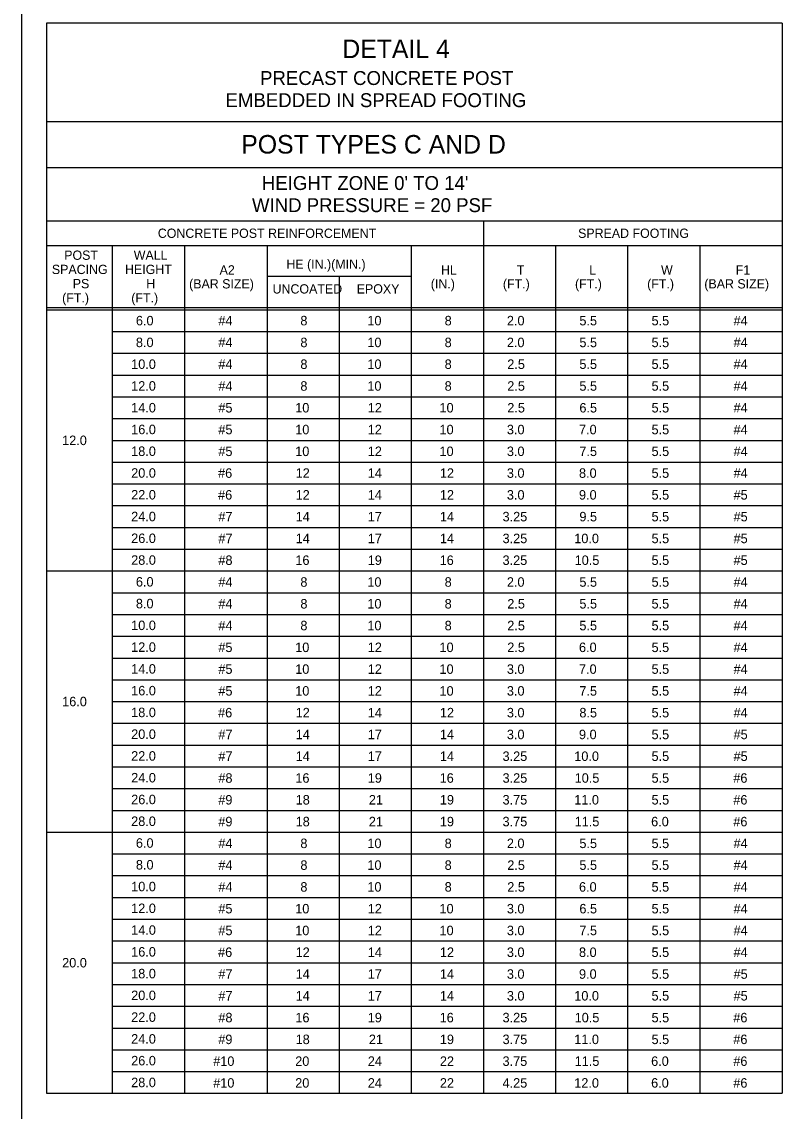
# Model space of a CAD drawing. Extents: x 3351 to 8430, y -3586 to 1457.
# Drawn here: x 6324.3 to 6570.3, y -2179.3 to -1826.9 of the extents above; entities that cross this region are included whole.
import ezdxf

# ---------------------------------------------------------------- set-up
doc = ezdxf.new("R2010")
doc.units = 0
doc.layers.add('1', color=7, linetype='Continuous')
doc.layers.add('2', color=7, linetype='Continuous')

msp = doc.modelspace()

# ---------------------------------------------------------------- linework, layer by layer
at = {"layer": '1'}
for p, q in [((6332.34, -1827.31), (6332.34, -2173.5)), ((6570.34, -1827.31), (6332.34, -1827.31)), ((6570.34, -1827.31), (6570.34, -2173.5)), ((6570.34, -1859.31), (6332.34, -1859.31)), ((6332.34, -1874.01), (6570.34, -1874.01)), ((6332.34, -1891.31), (6570.34, -1891.31)), ((6473.68, -1891.31), (6473.68, -2173.5)), ((6332.34, -1899.31), (6400.34, -1899.31)), ((6332.34, -1899.31), (6570.34, -1899.31)), ((6353.68, -2173.5), (6353.68, -1899.31)), ((6377.01, -1899.31), (6377.01, -2173.5)), ((6403.68, -1899.31), (6403.68, -2173.5)), ((6450.34, -1899.31), (6450.34, -2173.5)), ((6497.01, -1899.31), (6497.01, -2173.5)), ((6520.34, -1899.31), (6520.34, -2173.5)), ((6543.68, -1899.31), (6543.68, -2173.5)), ((6450.38, -1909.31), (6403.71, -1909.31)), ((6427.01, -1909.31), (6427.01, -2173.5)), ((6332.34, -1919.31), (6570.34, -1919.31)), ((6332.34, -1920.06), (6570.34, -1920.06)), ((6390.34, -1923.58), (6390.34, -1923.58)), ((6415.34, -1923.58), (6415.34, -1923.58)), ((6438.68, -1923.58), (6438.68, -1923.58)), ((6462.01, -1923.58), (6462.01, -1923.58)), ((6485.34, -1923.58), (6485.34, -1923.58)), ((6508.68, -1923.58), (6508.68, -1923.58)), ((6532.01, -1923.58), (6532.01, -1923.58)), ((6557.01, -1923.58), (6557.01, -1923.58)), ((6353.68, -1927.1), (6570.34, -1927.1)), ((6353.68, -1934.14), (6570.34, -1934.14)), ((6353.68, -1941.18), (6570.34, -1941.18)), ((6353.68, -1948.22), (6570.34, -1948.22)), ((6353.68, -1955.26), (6570.34, -1955.26)), ((6353.68, -1962.3), (6570.34, -1962.3)), ((6353.68, -1969.34), (6570.34, -1969.34)), ((6353.68, -1976.38), (6570.34, -1976.38)), ((6353.68, -1983.42), (6570.34, -1983.42)), ((6353.68, -1990.46), (6570.34, -1990.46)), ((6353.68, -1997.5), (6570.34, -1997.5)), ((6332.34, -2004.54), (6570.34, -2004.54)), ((6390.34, -2008.06), (6390.34, -2008.06)), ((6415.34, -2008.06), (6415.34, -2008.06)), ((6438.68, -2008.06), (6438.68, -2008.06)), ((6462.01, -2008.06), (6462.01, -2008.06)), ((6485.34, -2008.06), (6485.34, -2008.06)), ((6508.68, -2008.06), (6508.68, -2008.06)), ((6532.01, -2008.06), (6532.01, -2008.06)), ((6557.01, -2008.06), (6557.01, -2008.06)), ((6353.68, -2011.58), (6570.34, -2011.58)), ((6353.68, -2018.62), (6570.34, -2018.62)), ((6353.68, -2025.66), (6570.34, -2025.66)), ((6353.68, -2032.7), (6570.34, -2032.7)), ((6353.68, -2039.74), (6570.34, -2039.74)), ((6353.68, -2046.78), (6570.34, -2046.78)), ((6353.68, -2053.82), (6570.34, -2053.82)), ((6353.68, -2060.86), (6570.34, -2060.86)), ((6353.68, -2067.9), (6570.34, -2067.9)), ((6353.68, -2074.94), (6570.34, -2074.94)), ((6353.68, -2081.98), (6570.34, -2081.98)), ((6332.34, -2089.02), (6570.34, -2089.02)), ((6390.34, -2092.54), (6390.34, -2092.54)), ((6415.34, -2092.54), (6415.34, -2092.54)), ((6438.68, -2092.54), (6438.68, -2092.54)), ((6462.01, -2092.54), (6462.01, -2092.54)), ((6485.34, -2092.54), (6485.34, -2092.54)), ((6508.68, -2092.54), (6508.68, -2092.54)), ((6532.01, -2092.54), (6532.01, -2092.54)), ((6557.01, -2092.54), (6557.01, -2092.54)), ((6353.68, -2096.06), (6570.34, -2096.06)), ((6353.68, -2103.1), (6570.34, -2103.1)), ((6353.68, -2110.14), (6570.34, -2110.14)), ((6353.68, -2117.18), (6570.34, -2117.18)), ((6353.68, -2124.22), (6570.34, -2124.22)), ((6353.68, -2131.26), (6570.34, -2131.26)), ((6353.68, -2138.3), (6570.34, -2138.3)), ((6353.68, -2145.34), (6570.34, -2145.34)), ((6353.68, -2152.38), (6570.34, -2152.38)), ((6353.68, -2159.42), (6570.34, -2159.42)), ((6353.68, -2166.46), (6570.34, -2166.46)), ((6332.34, -2173.5), (6570.34, -2173.5))]:
    msp.add_line(p, q, dxfattribs=at)
at = {"layer": '2'}
msp.add_line((6324.34, -2383.31), (6324.34, -1819.31), dxfattribs=at)

# ---------------------------------------------------------------- texts
at = {"layer": '1'}
for s, height, p in [('DETAIL 4', 6, (6428.03, -1838.66)), ('PRECAST CONCRETE POST', 4.5, (6401.42, -1847.36)), ('EMBEDDED IN SPREAD FOOTING', 4.5, (6390.26, -1854.52)), ('POST TYPES C AND D', 6, (6395.34, -1869.54)), ("HEIGHT ZONE 0' TO 14'", 4.5, (6402, -1881.32)), ('WIND PRESSURE = 20 PSF', 4.5, (6398.81, -1888.48)), ('CONCRETE POST REINFORCEMENT', 3, (6368.35, -1896.81)), ('SPREAD FOOTING', 3, (6504.3, -1896.81)), ('POST', 3, (6338.07, -1903.91)), ('WALL', 3, (6360.56, -1903.91)), ('SPACING', 3, (6334.07, -1908.51)), ('HEIGHT', 3, (6357.73, -1908.51)), ('A2', 3, (6388.34, -1908.67)), ('HE (IN.)(MIN.)', 3, (6409.94, -1906.81)), ('HL', 3, (6459.97, -1908.67)), ('T', 3, (6484.49, -1908.67)), ('L', 3, (6507.94, -1908.67)), ('W', 3, (6531.14, -1908.67)), ('F1', 3, (6555.3, -1908.67)), ('PS', 3, (6340.83, -1913.11)), ('H', 3, (6364.61, -1913.11)), ('(BAR SIZE)', 3, (6378.47, -1913.17)), ('UNCOATED', 3, (6405.47, -1914.81)), ('EPOXY', 3, (6432.69, -1914.81)), ('(IN.)', 3, (6456.65, -1913.17)), ('(FT.)', 3, (6479.98, -1913.17)), ('(FT.)', 3, (6503.31, -1913.17)), ('(FT.)', 3, (6526.65, -1913.17)), ('(BAR SIZE)', 3, (6545.14, -1913.17)), ('(FT.)', 3, (6337.4, -1917.71)), ('(FT.)', 3, (6359.76, -1917.71)), ('6.0', 3.07, (6361.26, -1925.11)), ('#4', 3.07, (6387.94, -1925.11)), ('8', 3.07, (6414.47, -1925.11)), ('10', 3.07, (6436.14, -1925.11)), ('8', 3.07, (6461.14, -1925.11)), ('2.0', 3.07, (6481.27, -1925.11)), ('5.5', 3.07, (6504.73, -1925.11)), ('5.5', 3.07, (6528.07, -1925.11)), ('#4', 3.07, (6554.6, -1925.11)), ('8.0', 3.07, (6361.26, -1932.15)), ('#4', 3.07, (6387.94, -1932.16)), ('8', 3.07, (6414.47, -1932.16)), ('10', 3.07, (6436.14, -1932.16)), ('8', 3.07, (6461.14, -1932.16)), ('2.0', 3.07, (6481.27, -1932.16)), ('5.5', 3.07, (6504.73, -1932.16)), ('5.5', 3.07, (6528.07, -1932.16)), ('#4', 3.07, (6554.6, -1932.16)), ('10.0', 3.07, (6359.73, -1939.19)), ('#4', 3.07, (6387.94, -1939.2)), ('8', 3.07, (6414.47, -1939.2)), ('10', 3.07, (6436.14, -1939.2)), ('8', 3.07, (6461.14, -1939.2)), ('2.5', 3.07, (6481.4, -1939.2)), ('5.5', 3.07, (6504.73, -1939.2)), ('5.5', 3.07, (6528.07, -1939.2)), ('#4', 3.07, (6554.6, -1939.2)), ('12.0', 3.07, (6359.73, -1946.23)), ('#4', 3.07, (6387.94, -1946.25)), ('8', 3.07, (6414.47, -1946.25)), ('10', 3.07, (6436.14, -1946.25)), ('8', 3.07, (6461.14, -1946.25)), ('2.5', 3.07, (6481.4, -1946.25)), ('5.5', 3.07, (6504.73, -1946.25)), ('5.5', 3.07, (6528.07, -1946.25)), ('#4', 3.07, (6554.6, -1946.25)), ('14.0', 3.07, (6359.73, -1953.27)), ('#5', 3.07, (6387.94, -1953.29)), ('10', 3.07, (6412.8, -1953.29)), ('12', 3.07, (6436.27, -1953.29)), ('10', 3.07, (6459.47, -1953.29)), ('2.5', 3.07, (6481.4, -1953.29)), ('6.5', 3.07, (6504.73, -1953.29)), ('5.5', 3.07, (6528.07, -1953.29)), ('#4', 3.07, (6554.6, -1953.29)), ('16.0', 3.07, (6359.73, -1960.31)), ('#5', 3.07, (6387.94, -1960.34)), ('10', 3.07, (6412.8, -1960.34)), ('12', 3.07, (6436.27, -1960.34)), ('10', 3.07, (6459.47, -1960.34)), ('3.0', 3.07, (6481.27, -1960.34)), ('7.0', 3.07, (6504.6, -1960.34)), ('5.5', 3.07, (6528.07, -1960.34)), ('#4', 3.07, (6554.6, -1960.34)), ('12.0', 3.07, (6337.4, -1963.83)), ('18.0', 3.07, (6359.73, -1967.35)), ('#5', 3.07, (6387.94, -1967.38)), ('10', 3.07, (6412.8, -1967.38)), ('12', 3.07, (6436.27, -1967.38)), ('10', 3.07, (6459.47, -1967.38)), ('3.0', 3.07, (6481.27, -1967.38)), ('7.5', 3.07, (6504.73, -1967.38)), ('5.5', 3.07, (6528.07, -1967.38)), ('#4', 3.07, (6554.6, -1967.38)), ('20.0', 3.07, (6359.73, -1974.39)), ('#6', 3.07, (6387.85, -1974.42)), ('12', 3.07, (6412.94, -1974.42)), ('14', 3.07, (6436.27, -1974.42)), ('12', 3.07, (6459.6, -1974.42)), ('3.0', 3.07, (6481.27, -1974.42)), ('8.0', 3.07, (6504.6, -1974.42)), ('5.5', 3.07, (6528.07, -1974.42)), ('#4', 3.07, (6554.6, -1974.42)), ('22.0', 3.07, (6359.73, -1981.43)), ('#6', 3.07, (6387.85, -1981.47)), ('12', 3.07, (6412.94, -1981.47)), ('14', 3.07, (6436.27, -1981.47)), ('12', 3.07, (6459.6, -1981.47)), ('3.0', 3.07, (6481.27, -1981.47)), ('9.0', 3.07, (6504.6, -1981.47)), ('5.5', 3.07, (6528.07, -1981.47)), ('#5', 3.07, (6554.6, -1981.47)), ('24.0', 3.07, (6359.73, -1988.47)), ('#7', 3.07, (6387.94, -1988.51)), ('14', 3.07, (6412.94, -1988.51)), ('17', 3.07, (6436.27, -1988.51)), ('14', 3.07, (6459.6, -1988.51)), ('3.25', 3.07, (6479.87, -1988.51)), ('9.5', 3.07, (6504.73, -1988.51)), ('5.5', 3.07, (6528.07, -1988.51)), ('#5', 3.07, (6554.6, -1988.51)), ('26.0', 3.07, (6359.73, -1995.51)), ('#7', 3.07, (6387.94, -1995.56)), ('14', 3.07, (6412.94, -1995.56)), ('17', 3.07, (6436.27, -1995.56)), ('14', 3.07, (6459.6, -1995.56)), ('3.25', 3.07, (6479.87, -1995.56)), ('10.0', 3.07, (6503.07, -1995.56)), ('5.5', 3.07, (6528.07, -1995.56)), ('#5', 3.07, (6554.6, -1995.56)), ('28.0', 3.07, (6359.73, -2002.55)), ('#8', 3.07, (6387.94, -2002.6)), ('16', 3.07, (6412.85, -2002.6)), ('19', 3.07, (6436.26, -2002.6)), ('16', 3.07, (6459.52, -2002.6)), ('3.25', 3.07, (6479.87, -2002.6)), ('10.5', 3.07, (6503.2, -2002.6)), ('5.5', 3.07, (6528.07, -2002.6)), ('#5', 3.07, (6554.6, -2002.6)), ('6.0', 3.07, (6361.26, -2009.59)), ('#4', 3.07, (6387.94, -2009.65)), ('8', 3.07, (6414.47, -2009.65)), ('10', 3.07, (6436.14, -2009.65)), ('8', 3.07, (6461.14, -2009.65)), ('2.0', 3.07, (6481.27, -2009.65)), ('5.5', 3.07, (6504.73, -2009.65)), ('5.5', 3.07, (6528.07, -2009.65)), ('#4', 3.07, (6554.6, -2009.65)), ('8.0', 3.07, (6361.26, -2016.63)), ('#4', 3.07, (6387.94, -2016.69)), ('8', 3.07, (6414.47, -2016.69)), ('10', 3.07, (6436.14, -2016.69)), ('8', 3.07, (6461.14, -2016.69)), ('2.5', 3.07, (6481.4, -2016.69)), ('5.5', 3.07, (6504.73, -2016.69)), ('5.5', 3.07, (6528.07, -2016.69)), ('#4', 3.07, (6554.6, -2016.69)), ('10.0', 3.07, (6359.73, -2023.67)), ('#4', 3.07, (6387.94, -2023.74)), ('8', 3.07, (6414.47, -2023.74)), ('10', 3.07, (6436.14, -2023.74)), ('8', 3.07, (6461.14, -2023.74)), ('2.5', 3.07, (6481.4, -2023.74)), ('5.5', 3.07, (6504.73, -2023.74)), ('5.5', 3.07, (6528.07, -2023.74)), ('#4', 3.07, (6554.6, -2023.74)), ('12.0', 3.07, (6359.73, -2030.71)), ('#5', 3.07, (6387.94, -2030.78)), ('10', 3.07, (6412.8, -2030.78)), ('12', 3.07, (6436.27, -2030.78)), ('10', 3.07, (6459.47, -2030.78)), ('2.5', 3.07, (6481.4, -2030.78)), ('6.0', 3.07, (6504.6, -2030.78)), ('5.5', 3.07, (6528.07, -2030.78)), ('#4', 3.07, (6554.6, -2030.78)), ('14.0', 3.07, (6359.73, -2037.75)), ('#5', 3.07, (6387.94, -2037.82)), ('10', 3.07, (6412.8, -2037.82)), ('12', 3.07, (6436.27, -2037.82)), ('10', 3.07, (6459.47, -2037.82)), ('3.0', 3.07, (6481.27, -2037.82)), ('7.0', 3.07, (6504.6, -2037.82)), ('5.5', 3.07, (6528.07, -2037.82)), ('#4', 3.07, (6554.6, -2037.82)), ('16.0', 3.07, (6359.73, -2044.79)), ('#5', 3.07, (6387.94, -2044.87)), ('10', 3.07, (6412.8, -2044.87)), ('12', 3.07, (6436.27, -2044.87)), ('10', 3.07, (6459.47, -2044.87)), ('3.0', 3.07, (6481.27, -2044.87)), ('7.5', 3.07, (6504.73, -2044.87)), ('5.5', 3.07, (6528.07, -2044.87)), ('#4', 3.07, (6554.6, -2044.87)), ('16.0', 3.07, (6337.4, -2048.31)), ('18.0', 3.07, (6359.73, -2051.83)), ('#6', 3.07, (6387.85, -2051.91)), ('12', 3.07, (6412.94, -2051.91)), ('14', 3.07, (6436.27, -2051.91)), ('12', 3.07, (6459.6, -2051.91)), ('3.0', 3.07, (6481.27, -2051.91)), ('8.5', 3.07, (6504.73, -2051.91)), ('5.5', 3.07, (6528.07, -2051.91)), ('#4', 3.07, (6554.6, -2051.91)), ('20.0', 3.07, (6359.73, -2058.87)), ('#7', 3.07, (6387.94, -2058.96)), ('14', 3.07, (6412.94, -2058.96)), ('17', 3.07, (6436.27, -2058.96)), ('14', 3.07, (6459.6, -2058.96)), ('3.0', 3.07, (6481.27, -2058.96)), ('9.0', 3.07, (6504.6, -2058.96)), ('5.5', 3.07, (6528.07, -2058.96)), ('#5', 3.07, (6554.6, -2058.96)), ('22.0', 3.07, (6359.73, -2065.91)), ('#7', 3.07, (6387.94, -2066)), ('14', 3.07, (6412.94, -2066)), ('17', 3.07, (6436.27, -2066)), ('14', 3.07, (6459.6, -2066)), ('3.25', 3.07, (6479.87, -2066)), ('10.0', 3.07, (6503.07, -2066)), ('5.5', 3.07, (6528.07, -2066)), ('#5', 3.07, (6554.6, -2066)), ('24.0', 3.07, (6359.73, -2072.95)), ('#8', 3.07, (6387.94, -2073.05)), ('16', 3.07, (6412.85, -2073.05)), ('19', 3.07, (6436.26, -2073.05)), ('16', 3.07, (6459.52, -2073.05)), ('3.25', 3.07, (6479.87, -2073.05)), ('10.5', 3.07, (6503.2, -2073.05)), ('5.5', 3.07, (6528.07, -2073.05)), ('#6', 3.07, (6554.52, -2073.05)), ('26.0', 3.07, (6359.73, -2079.99)), ('#9', 3.07, (6387.92, -2080.09)), ('18', 3.07, (6412.94, -2080.09)), ('21', 3.07, (6436.62, -2080.09)), ('19', 3.07, (6459.59, -2080.09)), ('3.75', 3.07, (6479.87, -2080.09)), ('11.0', 3.07, (6503.07, -2080.09)), ('5.5', 3.07, (6528.07, -2080.09)), ('#6', 3.07, (6554.52, -2080.09)), ('28.0', 3.07, (6359.73, -2087.03)), ('#9', 3.07, (6387.92, -2087.14)), ('18', 3.07, (6412.94, -2087.14)), ('21', 3.07, (6436.62, -2087.14)), ('19', 3.07, (6459.59, -2087.14)), ('3.75', 3.07, (6479.87, -2087.14)), ('11.5', 3.07, (6503.2, -2087.14)), ('6.0', 3.07, (6527.94, -2087.14)), ('#6', 3.07, (6554.52, -2087.14)), ('6.0', 3.07, (6361.26, -2094.07)), ('#4', 3.07, (6387.94, -2094.18)), ('8', 3.07, (6414.47, -2094.18)), ('10', 3.07, (6436.14, -2094.18)), ('8', 3.07, (6461.14, -2094.18)), ('2.0', 3.07, (6481.27, -2094.18)), ('5.5', 3.07, (6504.73, -2094.18)), ('5.5', 3.07, (6528.07, -2094.18)), ('#4', 3.07, (6554.6, -2094.18)), ('8.0', 3.07, (6361.26, -2101.11)), ('#4', 3.07, (6387.94, -2101.22)), ('8', 3.07, (6414.47, -2101.22)), ('10', 3.07, (6436.14, -2101.22)), ('8', 3.07, (6461.14, -2101.22)), ('2.5', 3.07, (6481.4, -2101.22)), ('5.5', 3.07, (6504.73, -2101.22)), ('5.5', 3.07, (6528.07, -2101.22)), ('#4', 3.07, (6554.6, -2101.22)), ('10.0', 3.07, (6359.73, -2108.15)), ('#4', 3.07, (6387.94, -2108.27)), ('8', 3.07, (6414.47, -2108.27)), ('10', 3.07, (6436.14, -2108.27)), ('8', 3.07, (6461.14, -2108.27)), ('2.5', 3.07, (6481.4, -2108.27)), ('6.0', 3.07, (6504.6, -2108.27)), ('5.5', 3.07, (6528.07, -2108.27)), ('#4', 3.07, (6554.6, -2108.27)), ('12.0', 3.07, (6359.73, -2115.19)), ('#5', 3.07, (6387.94, -2115.31)), ('10', 3.07, (6412.8, -2115.31)), ('12', 3.07, (6436.27, -2115.31)), ('10', 3.07, (6459.47, -2115.31)), ('3.0', 3.07, (6481.27, -2115.31)), ('6.5', 3.07, (6504.73, -2115.31)), ('5.5', 3.07, (6528.07, -2115.31)), ('#4', 3.07, (6554.6, -2115.31)), ('14.0', 3.07, (6359.73, -2122.23)), ('#5', 3.07, (6387.94, -2122.36)), ('10', 3.07, (6412.8, -2122.36)), ('12', 3.07, (6436.27, -2122.36)), ('10', 3.07, (6459.47, -2122.36)), ('3.0', 3.07, (6481.27, -2122.36)), ('7.5', 3.07, (6504.73, -2122.36)), ('5.5', 3.07, (6528.07, -2122.36)), ('#4', 3.07, (6554.6, -2122.36)), ('16.0', 3.07, (6359.73, -2129.27)), ('#6', 3.07, (6387.85, -2129.4)), ('12', 3.07, (6412.94, -2129.4)), ('14', 3.07, (6436.27, -2129.4)), ('12', 3.07, (6459.6, -2129.4)), ('3.0', 3.07, (6481.27, -2129.4)), ('8.0', 3.07, (6504.6, -2129.4)), ('5.5', 3.07, (6528.07, -2129.4)), ('#4', 3.07, (6554.6, -2129.4)), ('20.0', 3.07, (6337.4, -2132.79)), ('18.0', 3.07, (6359.73, -2136.31)), ('#7', 3.07, (6387.94, -2136.45)), ('14', 3.07, (6412.94, -2136.45)), ('17', 3.07, (6436.27, -2136.45)), ('14', 3.07, (6459.6, -2136.45)), ('3.0', 3.07, (6481.27, -2136.45)), ('9.0', 3.07, (6504.6, -2136.45)), ('5.5', 3.07, (6528.07, -2136.45)), ('#5', 3.07, (6554.6, -2136.45)), ('20.0', 3.07, (6359.73, -2143.35)), ('#7', 3.07, (6387.94, -2143.49)), ('14', 3.07, (6412.94, -2143.49)), ('17', 3.07, (6436.27, -2143.49)), ('14', 3.07, (6459.6, -2143.49)), ('3.0', 3.07, (6481.27, -2143.49)), ('10.0', 3.07, (6503.07, -2143.49)), ('5.5', 3.07, (6528.07, -2143.49)), ('#5', 3.07, (6554.6, -2143.49)), ('22.0', 3.07, (6359.73, -2150.39)), ('#8', 3.07, (6387.94, -2150.54)), ('16', 3.07, (6412.85, -2150.54)), ('19', 3.07, (6436.26, -2150.54)), ('16', 3.07, (6459.52, -2150.54)), ('3.25', 3.07, (6479.87, -2150.54)), ('10.5', 3.07, (6503.2, -2150.54)), ('5.5', 3.07, (6528.07, -2150.54)), ('#6', 3.07, (6554.52, -2150.54)), ('24.0', 3.07, (6359.73, -2157.43)), ('#9', 3.07, (6387.92, -2157.58)), ('18', 3.07, (6412.94, -2157.58)), ('21', 3.07, (6436.62, -2157.58)), ('19', 3.07, (6459.59, -2157.58)), ('3.75', 3.07, (6479.87, -2157.58)), ('11.0', 3.07, (6503.07, -2157.58)), ('5.5', 3.07, (6528.07, -2157.58)), ('#6', 3.07, (6554.52, -2157.58)), ('26.0', 3.07, (6359.73, -2164.47)), ('#10', 3.07, (6386.27, -2164.63)), ('20', 3.07, (6412.8, -2164.63)), ('24', 3.07, (6436.27, -2164.63)), ('22', 3.07, (6459.6, -2164.63)), ('3.75', 3.07, (6479.87, -2164.63)), ('11.5', 3.07, (6503.2, -2164.63)), ('6.0', 3.07, (6527.94, -2164.63)), ('#6', 3.07, (6554.52, -2164.63)), ('28.0', 3.07, (6359.73, -2171.51)), ('#10', 3.07, (6386.27, -2171.67)), ('20', 3.07, (6412.8, -2171.67)), ('24', 3.07, (6436.27, -2171.67)), ('22', 3.07, (6459.6, -2171.67)), ('4.25', 3.07, (6479.87, -2171.67)), ('12.0', 3.07, (6503.07, -2171.67)), ('6.0', 3.07, (6527.94, -2171.67)), ('#6', 3.07, (6554.52, -2171.67))]:
    msp.add_text(s, height=height, dxfattribs=at).set_placement(p)

doc.saveas('drawing.dxf')
